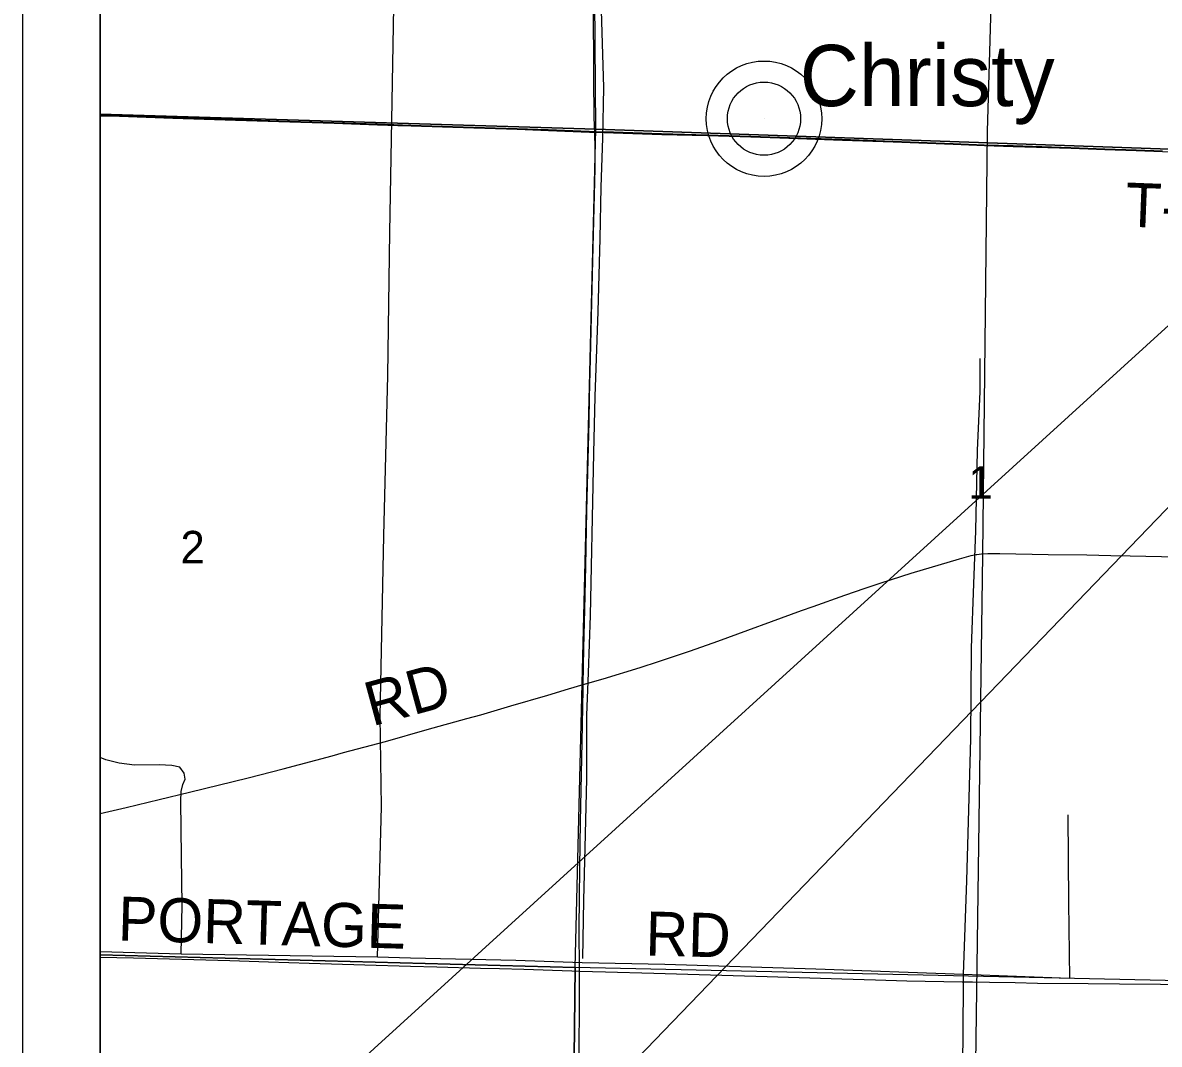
# Model space of a CAD drawing. Extents: x -59 to 43, y 0 to 22.
# Drawn here: x 23.417 to 24.882, y 14.155 to 15.472 of the extents above; entities that cross this region are included whole.
import ezdxf

# ---------------------------------------------------------------- set-up
doc = ezdxf.new("R2010")
doc.units = 0
for name, color, linetype in [('BR_P_Gen_Text', 7, 'Continuous'), ('Default', 7, 'Continuous'), ('GM_X_Interchange_Ramps', 7, 'Continuous'), ('GM_X_Minor_River', 7, 'Continuous'), ('GM_X_Rail_Line', 7, 'Continuous'), ('GM_X_Section', 7, 'Continuous'), ('GM_X_Section_Text', 7, 'Continuous'), ('GM_X_Township_Road', 7, 'Continuous'), ('GM_X_Township_Road_Text', 7, 'Continuous'), ('GM_X_Unincorporated', 7, 'Continuous'), ('GM_X_Unincorporated_Location', 7, 'Continuous'), ('GM_X_Unincorporated_Text', 7, 'Continuous'), ('SH_Data', 7, 'Continuous')]:
    doc.layers.add(name, color=color, linetype=linetype)

msp = doc.modelspace()

# ---------------------------------------------------------------- linework, layer by layer
at = {"layer": 'BR_P_Gen_Text'}
msp.add_lwpolyline([(26.7273, 16.7521), (23.5585, 13.8664), (23.9482, 13.8664)], close=True, dxfattribs=at)
at = {"layer": 'Default'}
for points in [[(23.5167, 16.3587), (23.5167, 15.3547), (24.1557, 15.3353), (24.1477, 16.3396)], [(23.5167, 15.3547), (23.5167, 14.2707), (24.1287, 14.2542), (24.1557, 15.3353)], [(23.5167, 14.2707), (23.5167, 14.1), (24.127, 14.1), (24.1287, 14.2542)], [(24.127, 14.1), (25.1417, 14.1), (25.1429, 14.1814), (25.1432, 14.2318), (24.1287, 14.2542)]]:
    msp.add_lwpolyline(points, close=True, dxfattribs=at)
at = {"layer": 'GM_X_Interchange_Ramps'}
for points in [[(23.5167, 20.9), (23.5167, 15.3531), (23.5414, 15.3524), (23.6098, 15.3502), (23.6905, 15.3475), (23.7465, 15.3457), (23.8179, 15.3435), (23.8738, 15.3416), (23.9172, 15.3401), (23.9979, 15.3374), (24.0539, 15.3356), (24.0942, 15.3342), (24.147, 15.3321), (24.1538, 15.3319), (24.1781, 15.3312), (24.2402, 15.3291), (24.2993, 15.3274), (24.3552, 15.3259), (24.3924, 15.3245), (24.4732, 15.3217), (24.5384, 15.3192), (24.616, 15.3163), (24.6563, 15.3146), (24.6934, 15.3136), (24.768, 15.3112), (24.8115, 15.3096), (24.8519, 15.3082), (24.886, 15.3068)], [(24.886, 15.3068), (24.8519, 15.3082), (24.8115, 15.3096), (24.768, 15.3112), (24.6934, 15.3136), (24.6563, 15.3146), (24.616, 15.3163), (24.5384, 15.3192), (24.4732, 15.3217), (24.3924, 15.3245), (24.3552, 15.3259), (24.2993, 15.3274), (24.2402, 15.3291), (24.1781, 15.3312), (24.1538, 15.3319), (24.147, 15.3321), (24.0942, 15.3342), (24.0539, 15.3356), (23.9979, 15.3374), (23.9172, 15.3401), (23.8738, 15.3416), (23.8179, 15.3435), (23.7465, 15.3457), (23.6905, 15.3475), (23.6098, 15.3502), (23.5414, 15.3524), (23.5167, 15.3531), (23.5167, 14.1)]]:
    msp.add_lwpolyline(points, dxfattribs=at)
at = {"layer": 'GM_X_Minor_River'}
for points in [[(23.8739, 14.2674), (23.879, 14.4615), (23.8775, 14.5785), (23.882, 14.811), (23.8872, 15.0176), (23.89, 15.2026), (23.8927, 15.3466), (23.8951, 15.4928), (23.8975, 15.6493), (23.9005, 15.7884), (23.9028, 15.9286), (23.9042, 16.0106), (23.9026, 16.0866), (23.9024, 16.1417), (23.9037, 16.2044), (23.9039, 16.2651)], [(24.1622, 15.4882), (24.1653, 15.3891), (24.1643, 15.3237), (24.1619, 15.2603), (24.1605, 15.1942), (24.158, 15.1), (24.1542, 14.9906), (24.1525, 14.9173), (24.1507, 14.8341), (24.1494, 14.7714), (24.148, 14.708), (24.1455, 14.6343), (24.1435, 14.5796), (24.1436, 14.4976), (24.1411, 14.4087), (24.1397, 14.3411), (24.1383, 14.2659)], [(24.6276, 14.1), (24.629, 14.1607), (24.6296, 14.2454), (24.6338, 14.3662), (24.6389, 14.5489), (24.6397, 14.6663), (24.6429, 14.7491), (24.6454, 14.8174), (24.6476, 14.9208), (24.6509, 14.9971), (24.651, 15.0396)], [(23.6208, 14.2716), (23.6222, 14.3347), (23.6212, 14.3973), (23.6203, 14.4688), (23.6211, 14.4813), (23.623, 14.49), (23.6261, 14.4972), (23.625, 14.5048), (23.619, 14.5125), (23.6091, 14.5148), (23.5924, 14.5156), (23.5609, 14.5149), (23.5408, 14.5176), (23.5237, 14.5219), (23.5167, 14.525)], [(24.7638, 14.4509), (24.765, 14.3381), (24.7662, 14.2401), (24.6296, 14.2454), (24.4392, 14.2521), (24.2446, 14.258), (24.1379, 14.2602), (24.0522, 14.2631), (23.9164, 14.2662), (23.8739, 14.2674), (23.6208, 14.2716), (23.5167, 14.2746)]]:
    msp.add_lwpolyline(points, dxfattribs=at)
at = {"layer": 'GM_X_Rail_Line'}
msp.add_lwpolyline([(24.8595, 17.5703), (24.845, 16.9588), (24.842, 16.884), (24.8319, 16.8415), (24.8198, 16.8142), (24.7955, 16.7879), (24.6985, 16.7162), (24.6793, 16.6808), (24.6733, 16.6535), (24.6733, 15.7893), (24.6598, 15.3324), (24.6541, 14.7866), (24.6444, 14.1)], dxfattribs=at)
at = {"layer": 'GM_X_Section'}
for points in [[(24.1477, 16.3396), (25.173, 16.308), (25.1744, 16.294), (25.1667, 15.3001), (24.1557, 15.3353)], [(24.1557, 15.3353), (25.1667, 15.3001), (25.1432, 14.2318), (24.1287, 14.2542)]]:
    msp.add_lwpolyline(points, close=True, dxfattribs=at)
at = {"layer": 'GM_X_Township_Road'}
msp.add_line((24.6345, 14.2356), (24.6412, 14.2356), dxfattribs=at)
for points in [[(24.154, 15.3313), (24.1533, 15.3498), (24.1528, 15.4026), (24.1519, 15.5954), (24.1515, 15.67), (24.1511, 15.726), (24.151, 15.7913), (24.1511, 15.8022)], [(23.5167, 15.3525), (23.5416, 15.3518), (23.61, 15.3496), (23.6908, 15.3469), (23.7467, 15.3452), (23.8181, 15.3429), (23.874, 15.341), (23.9002, 15.3401)], [(23.9002, 15.3401), (23.9174, 15.3395), (23.9982, 15.3369), (24.0541, 15.335), (24.0945, 15.3337), (24.1473, 15.3315), (24.154, 15.3313)], [(24.1393, 14.6191), (24.1401, 14.666), (24.1414, 14.7158), (24.1427, 14.7717), (24.144, 14.8432), (24.1467, 14.9582), (24.1474, 14.9893), (24.1485, 15.039), (24.1516, 15.1665), (24.1536, 15.2504), (24.1545, 15.2846), (24.1546, 15.3125), (24.1541, 15.328), (24.154, 15.3313)], [(24.154, 15.3313), (24.1784, 15.3306), (24.2405, 15.3285), (24.2995, 15.3269), (24.3554, 15.3253), (24.3927, 15.3239), (24.4734, 15.3211), (24.5386, 15.3187), (24.6163, 15.3158), (24.6565, 15.3141), (24.6936, 15.313), (24.7682, 15.3106), (24.8117, 15.309), (24.8521, 15.3077), (24.8862, 15.3063), (24.9577, 15.3034), (25.0601, 15.299), (25.113, 15.2972), (25.1492, 15.2957)], [(24.1393, 14.6191), (24.1651, 14.6266), (24.2128, 14.6409), (24.2364, 14.6486), (24.2776, 14.6627), (24.3128, 14.675), (24.4208, 14.7144), (24.4355, 14.7195), (24.4764, 14.7342), (24.5028, 14.7435), (24.5234, 14.7504), (24.562, 14.7626), (24.6245, 14.7813), (24.6395, 14.7855), (24.6455, 14.7868), (24.6465, 14.7869)], [(24.6465, 14.7869), (24.6525, 14.7877), (24.661, 14.7881), (24.6765, 14.7879), (24.7387, 14.7867), (24.7884, 14.7862), (24.8195, 14.7855), (24.8443, 14.785), (24.8847, 14.7842), (24.9717, 14.7825), (25.0245, 14.7814), (25.0587, 14.7808), (25.1532, 14.7785)], [(23.5167, 14.4527), (23.5502, 14.4606), (23.5925, 14.4709), (23.6318, 14.4801), (23.7073, 14.4987), (23.7524, 14.5103), (23.7944, 14.5216), (23.8155, 14.5271), (23.8304, 14.5314), (23.8844, 14.5458), (23.9382, 14.5611), (23.9892, 14.5751), (24.0071, 14.5802), (24.0458, 14.5917), (24.0936, 14.6055), (24.1204, 14.6136), (24.1393, 14.6191)], [(24.1343, 14.2495), (24.134, 14.3054), (24.1345, 14.3427), (24.135, 14.3831), (24.1358, 14.4422), (24.1379, 14.5448), (24.1392, 14.6132), (24.1393, 14.6191)], [(23.5167, 14.2675), (23.5594, 14.2665), (23.6836, 14.2631), (23.7333, 14.2617), (23.7861, 14.26), (23.8575, 14.2576), (23.9165, 14.2559), (23.9507, 14.2552), (24.0066, 14.2535), (24.0315, 14.2528), (24.0625, 14.252), (24.1246, 14.2498), (24.1343, 14.2495)], [(24.1337, 14.1), (24.134, 14.1406), (24.1345, 14.2121), (24.1343, 14.2495)], [(24.1343, 14.2495), (24.1681, 14.2485), (24.2302, 14.2469), (24.3762, 14.2424), (24.4725, 14.2396), (24.5159, 14.2382), (24.5563, 14.2372), (24.6278, 14.2356), (24.6345, 14.2356)], [(24.6412, 14.2356), (24.6628, 14.2354), (24.6959, 14.2348)], [(24.6959, 14.2348), (24.7249, 14.2342), (24.7902, 14.2334), (24.8306, 14.2332), (24.8834, 14.2326), (24.8958, 14.2322), (24.9206, 14.2317), (24.9671, 14.2306), (25.0075, 14.2297), (25.0218, 14.2293)]]:
    msp.add_lwpolyline(points, dxfattribs=at)
at = {"layer": 'GM_X_Unincorporated'}
for radius in [0.0744, 0.0472]:
    msp.add_circle((24.3723, 15.3487), radius, dxfattribs=at)
at = {"layer": 'GM_X_Unincorporated_Location'}
msp.add_line((24.3723, 15.3487), (24.3723, 15.3487), dxfattribs=at)
at = {"layer": 'SH_Data'}
for points in [[(23.4167, 21), (30.4167, 21), (30.4167, 14), (23.4167, 14)], [(23.5167, 20.9), (30.3167, 20.9), (30.3167, 14.1), (23.5167, 14.1)]]:
    msp.add_lwpolyline(points, close=True, dxfattribs=at)

# ---------------------------------------------------------------- texts
at = {"layer": 'GM_X_Section_Text'}
for s, p in [('1', (24.6359, 14.8587)), ('2', (23.6201, 14.7753))]:
    msp.add_text(s, height=0.0419, rotation=0, dxfattribs=at).set_placement(p)
at = {"layer": 'GM_X_Township_Road_Text'}
for s, rotation, p in [('T-177', 357.7543, (24.8372, 15.2097)), ('RD', 15.2121, (23.8669, 14.5649)), ('PORTAGE', 358.3556, (23.5389, 14.289)), ('RD', 358.5194, (24.219, 14.2698))]:
    msp.add_text(s, height=0.05682, rotation=rotation, dxfattribs=at).set_placement(p)
at = {"layer": 'GM_X_Unincorporated_Text'}
msp.add_text('Christy', height=0.07898, rotation=0, dxfattribs=at).set_placement((24.4184, 15.3649))

doc.saveas('drawing.dxf')
